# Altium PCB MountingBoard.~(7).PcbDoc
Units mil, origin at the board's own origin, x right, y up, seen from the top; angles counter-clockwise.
Board outline 3780 x 10000 mil, 4 copper layers (Top Layer, Internal Plane 1, Internal Plane 2, Bottom Layer); 27 components, 8 nets, 108 pads, 8 vias.
Unrouted connection lines stored in the file: 83.
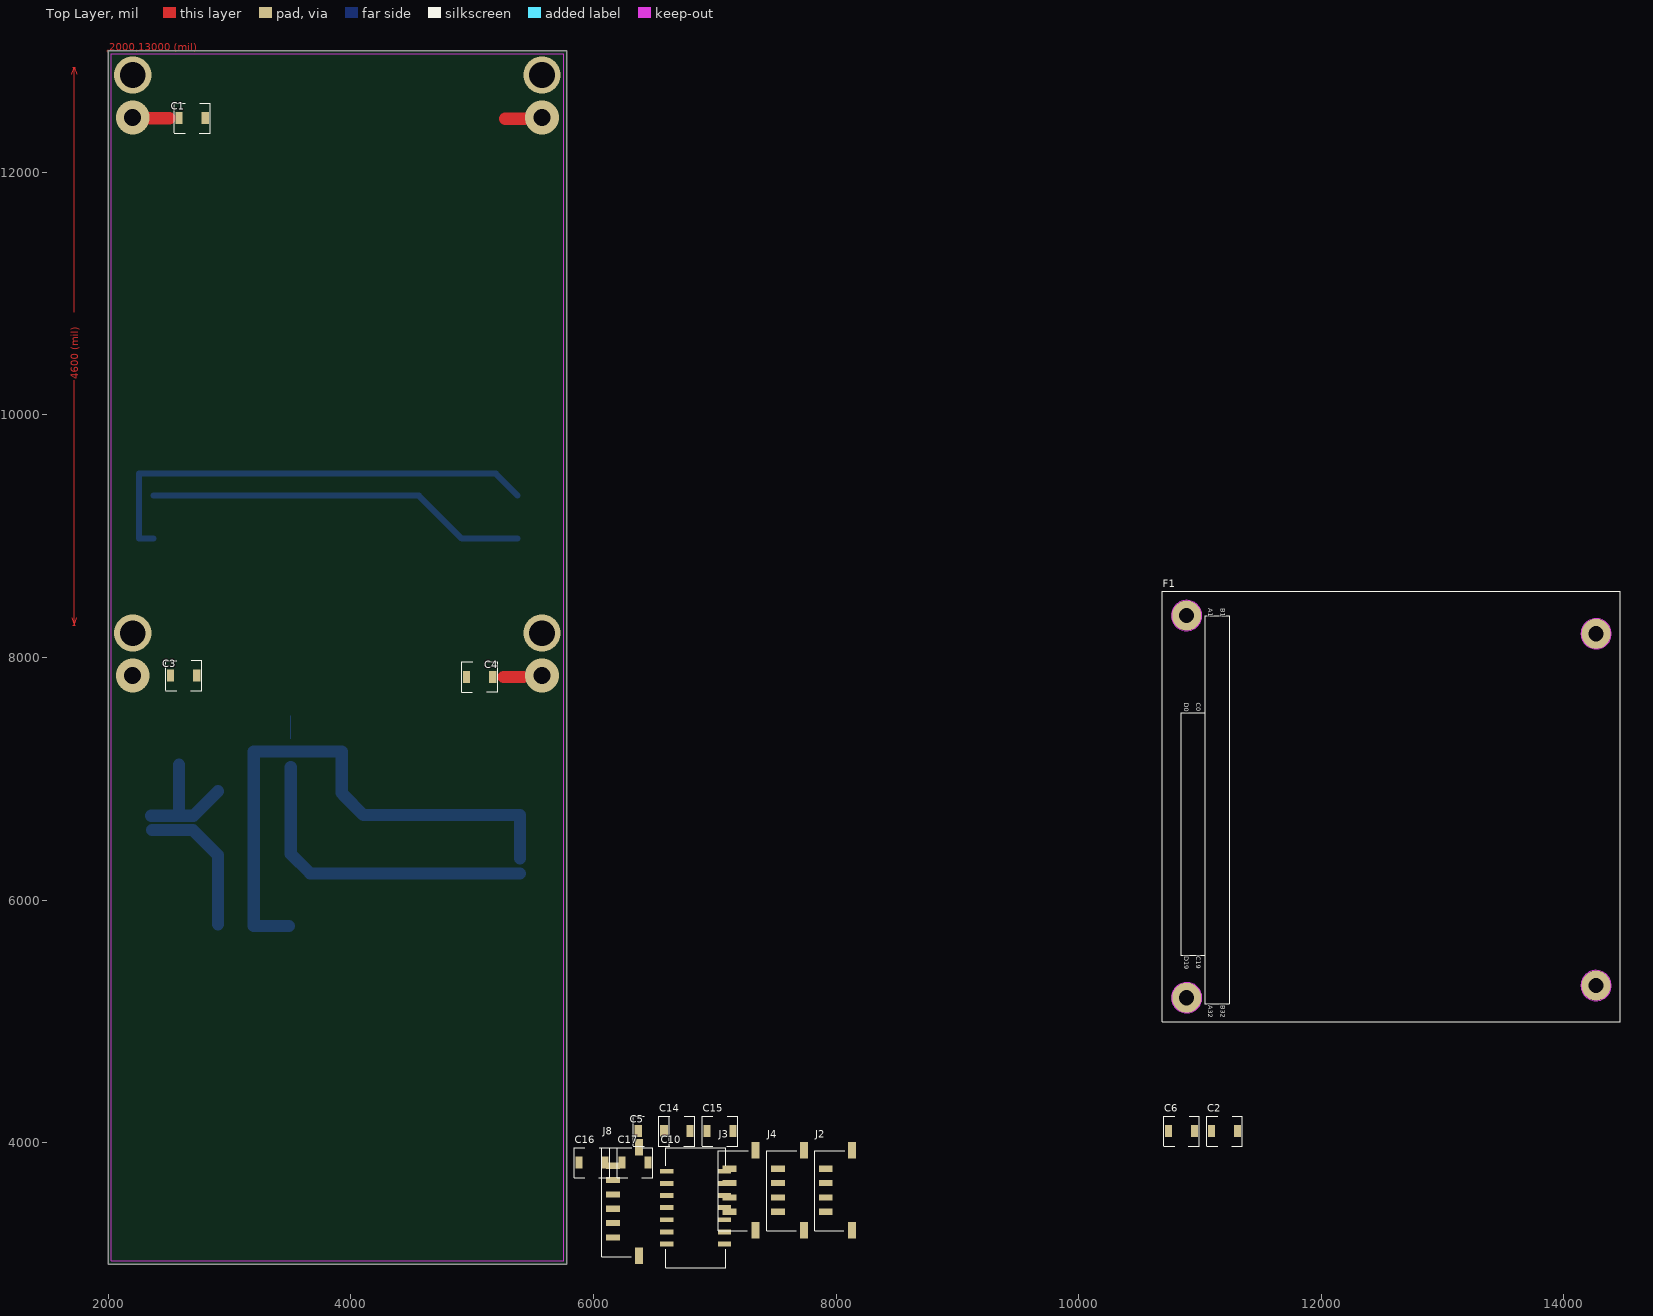
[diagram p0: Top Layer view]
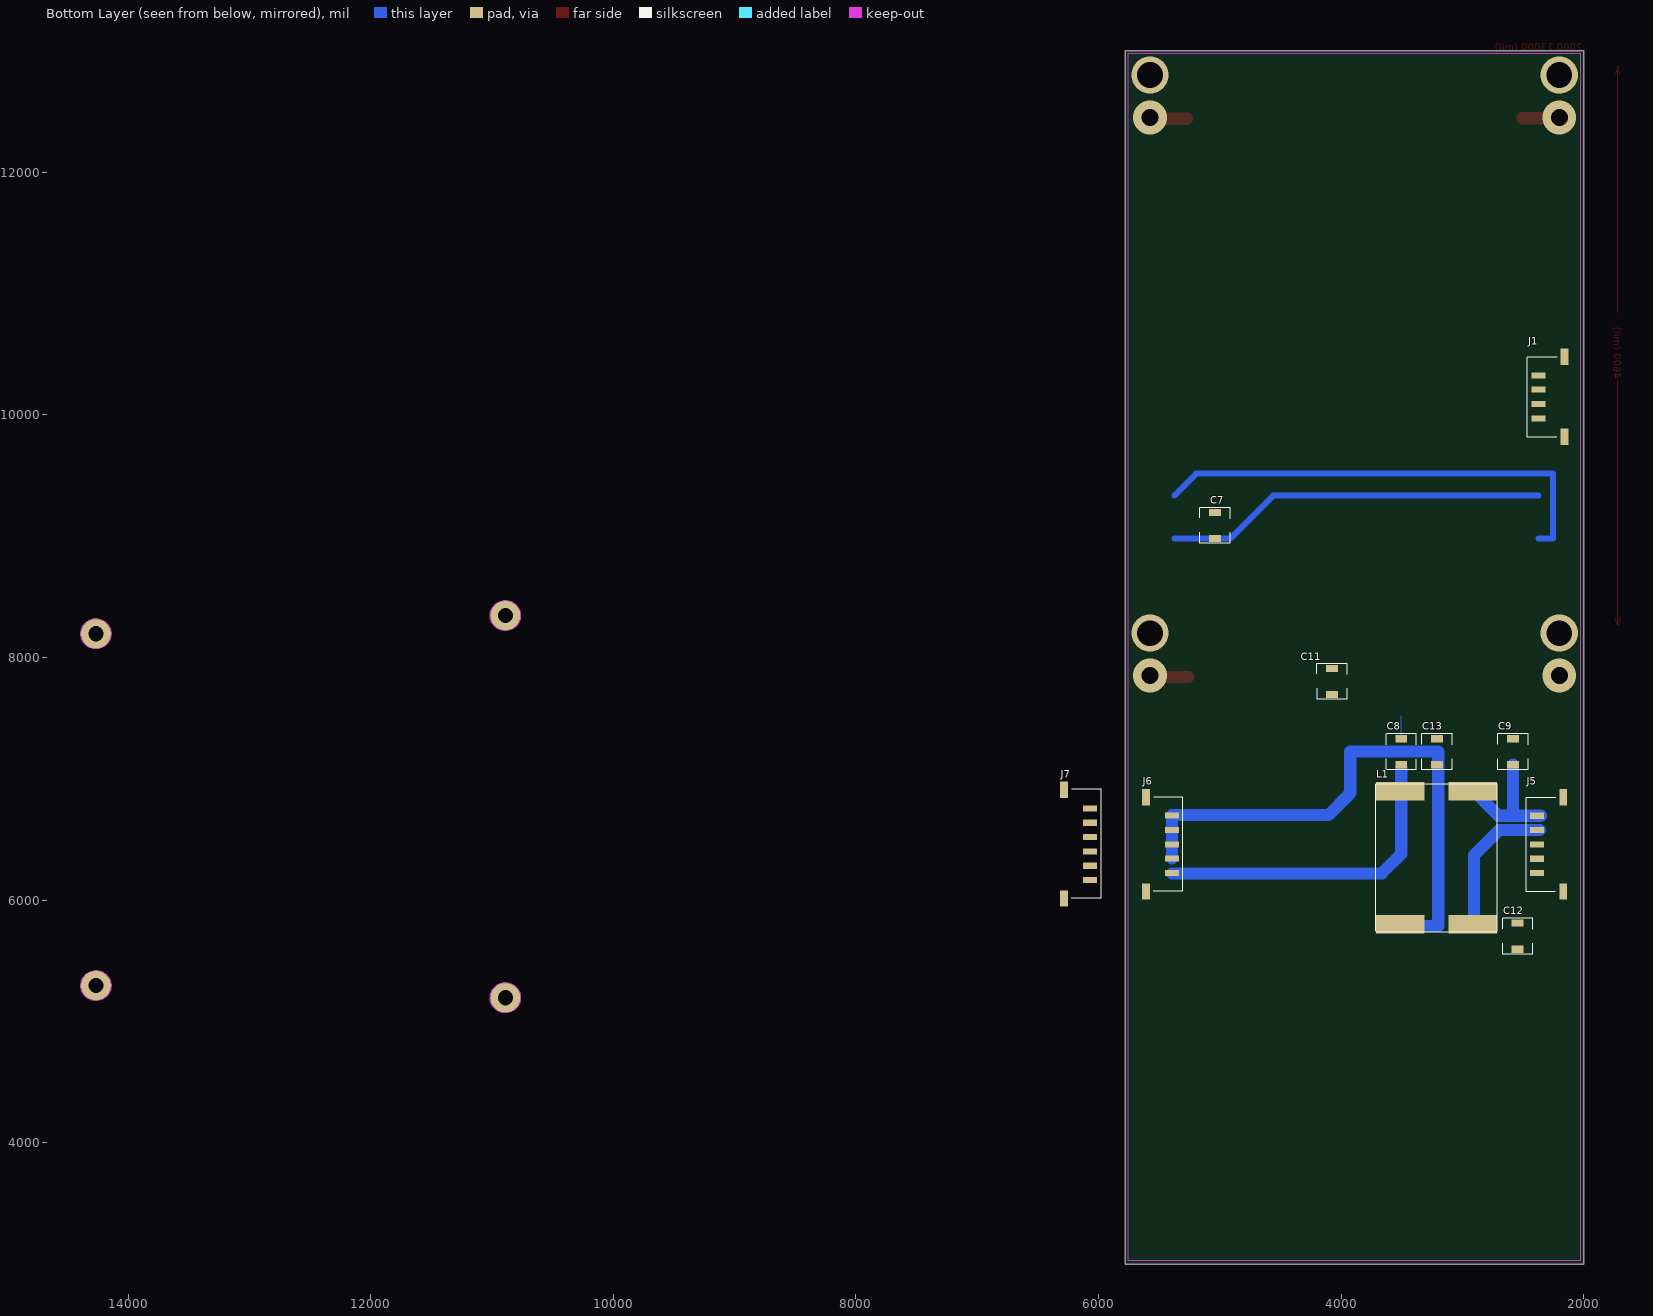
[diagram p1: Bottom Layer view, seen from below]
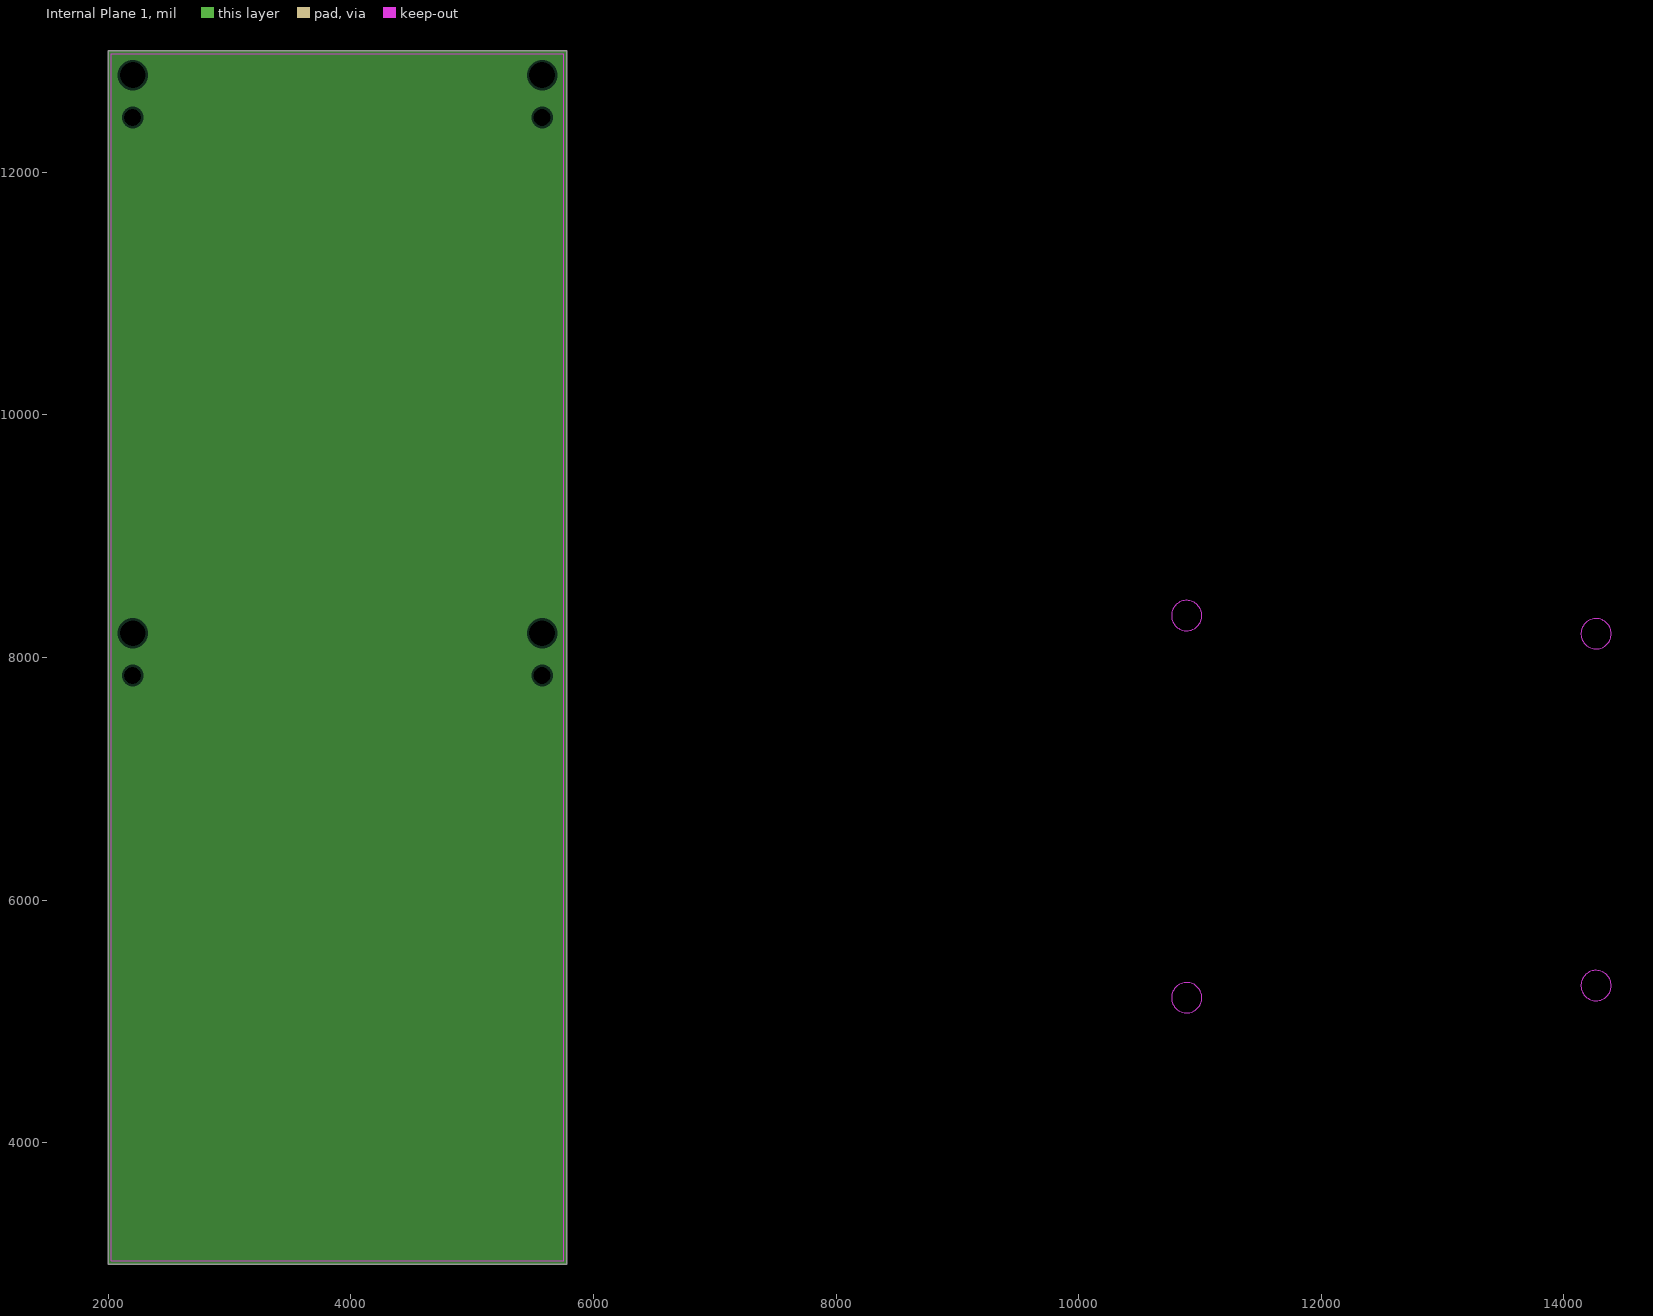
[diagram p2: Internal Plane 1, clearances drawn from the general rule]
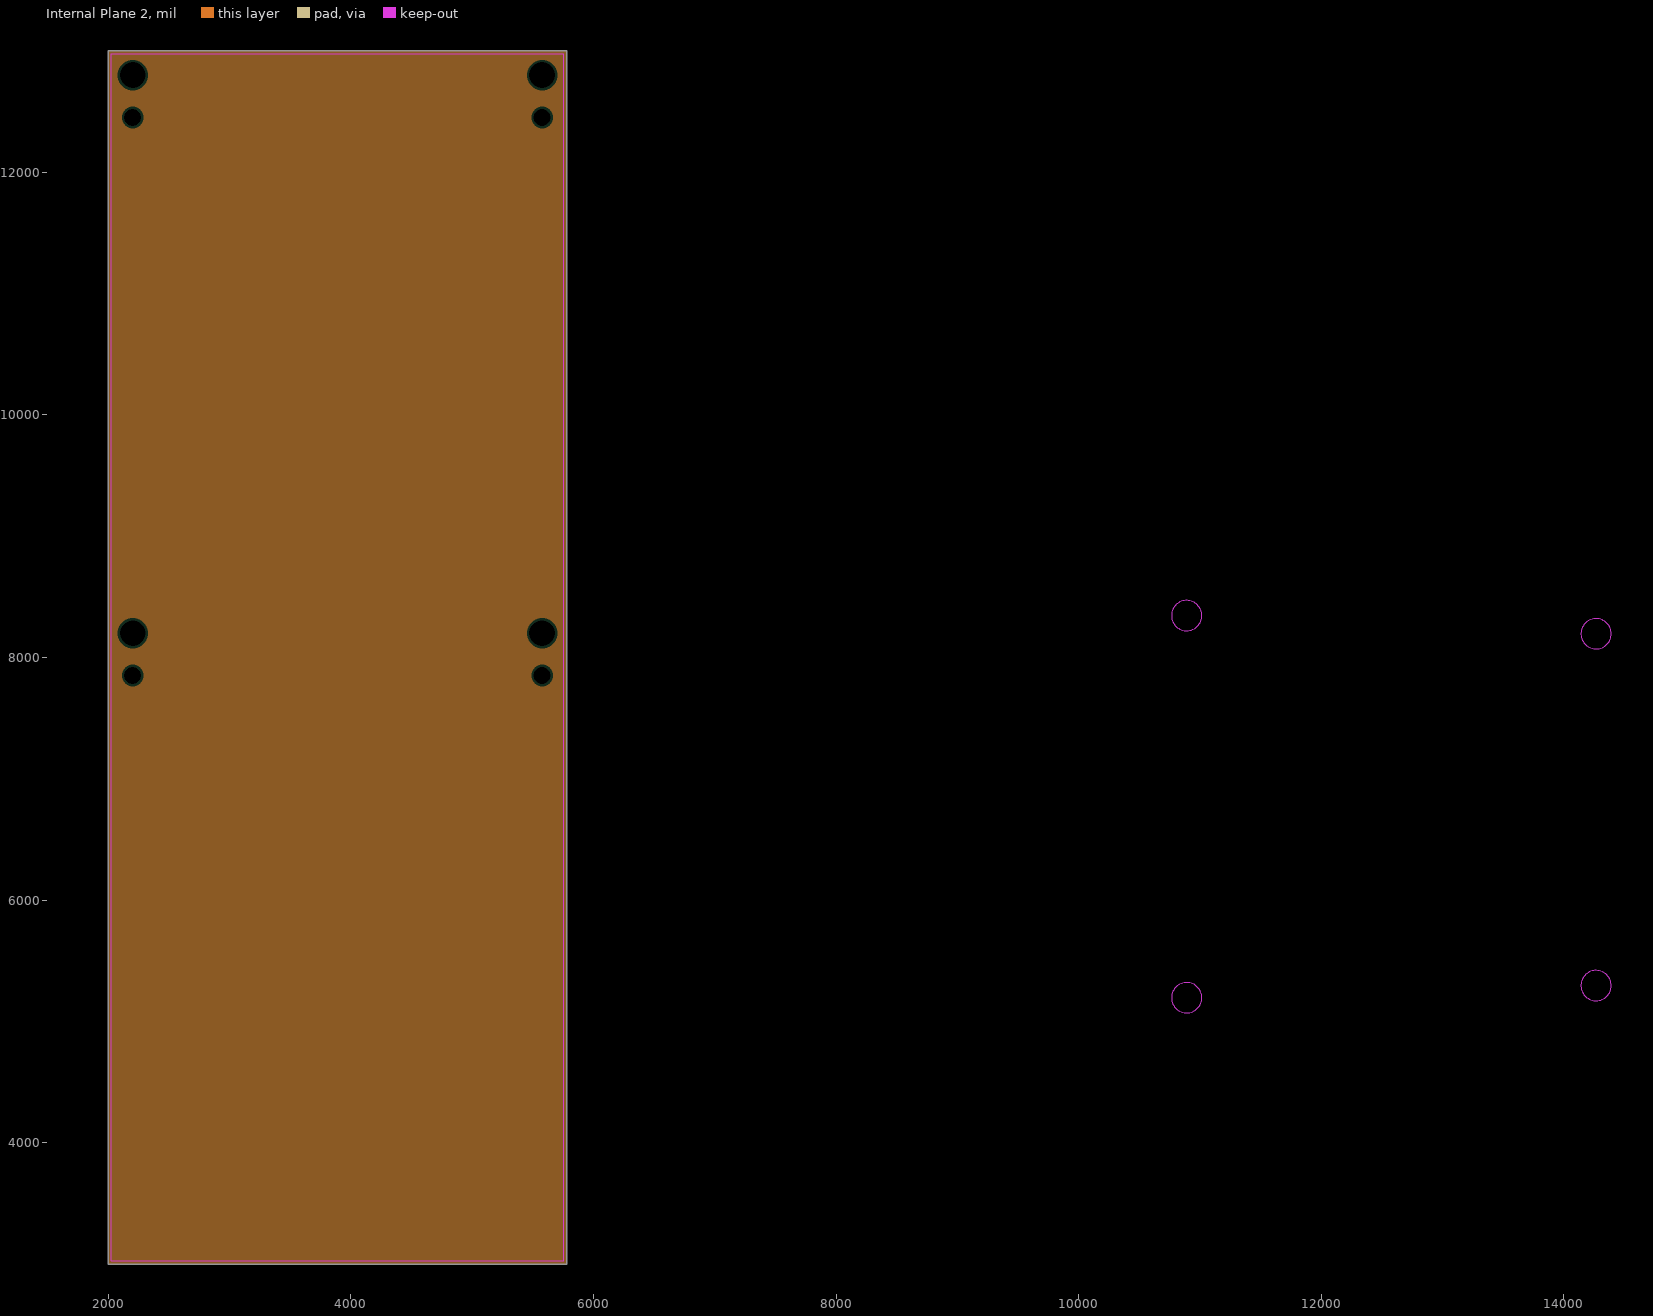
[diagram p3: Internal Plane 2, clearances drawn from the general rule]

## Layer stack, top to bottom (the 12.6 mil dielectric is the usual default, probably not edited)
Top Layer: signal copper 1.4
Dielectric: dielectric 12.6, FR-4, Dk 4.8
Internal Plane 1: plane copper 1.4
Dielectric: dielectric 12.6, FR-4, Dk 4.8
Internal Plane 2: plane copper 1.4
Dielectric: dielectric 12.6, FR-4, Dk 4.8
Bottom Layer: signal copper 1.4

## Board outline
2000,3000 5780,3000 5780,13000 2000,13000

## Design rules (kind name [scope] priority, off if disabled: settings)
Clearance [All] p1: gap=8
PlaneClearance [All] p1: clearance=20
PlaneConnect [All] p1: planeconnectstyle=Direct reliefexpansion=20 reliefentries=4 reliefconductorwidth=10 reliefairgap=10
PolygonConnect [All] p1: connectstyle=Direct reliefconductorwidth=10 reliefentries=4 polygonreliefangle="90 Angle"
RoomDefinition MountingBoard [InComponentClass('MountingBoard')] p1: confinementstyle=ConfineIn formatcopy=TRUE lockcomponents=FALSE outline 5825,2960 7145,2960 7145,4075 5825,4075
RoutingVias [All] p1: holewidth=28 width=50 viastyle="Through Hole" minholewidth=28 minwidth=50 maxholewidth=28 maxwidth=50
SilkscreenOverComponentPads [All] p1: minsilkscreentomaskgap=10
SolderMaskExpansion [All] p1: expansion=4
Width [All] p1: maxlimit=100 minlimit=10 preferedwidth=10 toplayer_maxwidth=10 minimp=50.000000 maximp=50.000000 favimp=50.000000
25 further rules are at their usual default settings.

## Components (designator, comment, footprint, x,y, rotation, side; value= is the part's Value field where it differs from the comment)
C1 "Cap Semi" 7163 2585,12445 r0 top
C2 "Cap Semi" 7163 11095,4095 r0 top
C3 "Cap Semi" 7163 2515,7850 r0 top
C4 "Cap Semi" 7163 5170,7840 r180 top
C5 "Cap Semi" 7163 6370,4095 r0 top
C6 "Cap Semi" 7163 10740,4095 r0 top
C7 "Cap Semi" 7163 5040,8980 r90 bottom
C8 "Cap Semi" 7163 3505,7330 r270 bottom
C9 "Cap Semi" 7163 2585,7115 r90 bottom
C10 "10uf" CAPSTICK-CS4-7-SMD 6605,3165 r90 top
C11 "Cap Semi" 7163 4075,7695 r90 bottom
C12 "Cap Semi" 7163 2545,5595 r90 bottom
C13 "Cap Semi" 7163 3210,7115 r90 bottom
C14 "Cap Semi" 7163 6580,4095 r0 top
C15 "Cap Semi" 7163 6935,4095 r0 top
C16 "Cap Semi" 7163 5880,3835 r0 top
C17 "Cap Semi" 7163 6235,3835 r0 top
F1 "PC104 Footprint" "PC104 Footprint" 10895,8345 r270 top
J1 "CON4_SMD" "Microfit3-1x4 SMT RA Nail" 2375,10325 r90 bottom
J2 "CON4_SMD" "Microfit3-1x4 SMT RA Nail" 7915,3785 r90 top
J3 "CON4_SMD" "Microfit3-1x4 SMT RA Nail" 7120,3785 r90 top
J4 "CON4_SMD" "Microfit3-1x4 SMT RA Nail" 7520,3785 r90 top
J5 "CON5_SMD" "Microfit3-1x5 SMT RA Nail" 2385,6695 r90 bottom locked
J6 "CON5_SMD" "Microfit3-1x5 SMT RA Nail" 5395,6223 r270 bottom locked
J7 "CON6_SMD" "Microfit3-1x6 SMT RA Nail" 6070,6165 r270 bottom
J8 "CON6_SMD" "Microfit3-1x6 SMT RA Nail" 6160,3810 r90 top
L1 "" Pulse_BigFoot 2715,6975 r270 bottom

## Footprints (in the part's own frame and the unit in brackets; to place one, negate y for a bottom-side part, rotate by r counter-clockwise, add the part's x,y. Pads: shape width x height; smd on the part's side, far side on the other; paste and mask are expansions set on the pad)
7163 [mm] "7.1 x 6.3 SMD"
  rect 1.5x2.5 smd: 1(0,0) 2(5.461,0)
  silkscreen extent -1.02,-3.17 6.48,3.17
CAPSTICK-CS4-7-SMD [mil] "Capstick CS4 case with 7 leads per side"
  rect 40x110 smd: 1(0,0) 1(100,0) 1(200,0) 1(300,0) 1(400,0) 1(500,0) 1(600,0) 2(0,-475) 2(100,-475) 2(200,-475) 2(300,-475) 2(400,-475) 2(500,-475) 2(600,-475)
  silkscreen extent -195,-485 795,10
"Microfit3-1x4 SMT RA Nail" [mil] "Microfit 3 Single Row 4 Position SMT Right Angle Nail"
  rect 50x115 smd: 1(0,0) 2(-118.11,0) 3(-236.22,0) 4(-354.33,0)
  rect 135x65 smd: nail(-506.5,-215.5) nail(152.5,-215.5)
  silkscreen extent -510,-155 150,90
"Microfit3-1x5 SMT RA Nail" [mil] "Microfit 3.0 Single Row SMT with Nails 5 Position"
  rect 50x115 smd: 1(0,0) 2(-118.11,0) 3(-236.22,0) 4(-354.33,0) 5(-472.44,0)
  rect 135x65 smd: nail(-624.5,-215.5) nail(152.5,-215.5)
  silkscreen extent -625,-155 150,90
"Microfit3-1x6 SMT RA Nail" [mil] "Microfit 3 Single Row 6 Position SMT Right Angle Nail"
  rect 50x115 smd: 1(0,0) 2(-118.11,0) 3(-236.22,0) 4(-354.33,0) 5(-472.44,0) 6(-590.55,0)
  rect 135x65 smd: nail(-743.5,-215.5) nail(152.5,-215.5)
  silkscreen extent -750,-155 150,90
"PC104 Footprint" [mil] "PC104 Footprint"
  round 250 hole 125: Mnt1(0,-5) Mnt2(3150,-5) Mnt3(3050,3370) Mnt4(150,3370)
  Keep-Out Layer circle w10: c0,-5 r125
  Keep-Out Layer circle w10: c150,3370 r125
  Keep-Out Layer circle w10: c3050,3370 r125
  Keep-Out Layer circle w10: c3150,-5 r125
  silkscreen extent -200,-205 3350,3570
Pulse_BigFoot [mil] "Pulse engineering big foot footprint"
  rect 155x400 smd: 1(77.5,-200) 2(77.5,-800) 3(1174.5,-200) 4(1174.5,-800)
  silkscreen extent 20,-1000 1240,0

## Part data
C1 C2 C3 C4 C5 C6 C7 C8 C9 C11 C12 C13 C14 C15 C16 C17: "Capacitor (Semiconductor SIM Model)"
C10: library part CAPACITOR, "Capacitor"
L1: library part "COMMON MODE CHOKE"

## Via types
v1: diameter 280, hole 140, Top Layer to Bottom Layer, 4 vias
v2: diameter 306, hole 213, Top Layer to Bottom Layer, 4 vias

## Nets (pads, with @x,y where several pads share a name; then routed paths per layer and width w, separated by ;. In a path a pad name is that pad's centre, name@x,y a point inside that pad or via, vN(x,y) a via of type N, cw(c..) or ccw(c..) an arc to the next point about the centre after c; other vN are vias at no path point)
48V+: C9.1 J5.1 L1.1 | length 1038.9
  Bottom Layer w100: J5.1@2355,6695 J5.1 2697.5,6695 ; 2585,6705 C9.1 ; 2702.5,6695 L1.1@2905,6897.5
48V-: C12.2 J5.2 L1.3 | length 1200.2
  Bottom Layer w100: J5.2@2360,6576.89 2698.11,6576.89 2905,6370 L1.3@2905,5800.5
+5V: C1.1 C7.1 C14.2 C15.2 J1.1 J2.1 J3.1 J4.1 J7.5 J7.6 J8.5 J8.6 | length 3146.6
  Bottom Layer w50: 2375,9334 4561,9334 4915,8980 5375,8980
+12V: C6.2 C11.2 C16.2 J1.4 J2.4 J3.4 J4.4 J7.4 J8.4
-12V: C17.2 J7.3 J8.3
CHASSIS: C1.2 C2.1 C3.1 C4.1 C5.1 C6.1 C7.2 C8.1 C9.2 C11.1 C12.1 C13.2 C14.1 C15.1 C16.1 C17.1 J1.nail J2.nail J3.nail J4.nail J7.nail J8.nail | length 351.9
  Top Layer w100: 5260,7840 5421.85,7840
  Bottom Layer w10: C8.1 3505,7520
  other v1: 2202.5,7850 5577.5,7850
"EDGETECH GROUND": C2.2 C3.2 C4.2 C5.2 C10.2 C13.1 J1.2 J1.3 J2.2 J2.3 J3.2 J3.3 J4.2 J4.3 J6.2 J6.3 J6.4 J6.5 J7.1 J7.2 J8.1 J8.2 L1.4 | length 4683.8
  Bottom Layer w100: L1.4@3489.5,5785 3200,5785 3200,7225 3925,7225 3925,6885 ; 3935,6870 4105,6700 5395,6700 J6.2
  other v2: 2202.5,8200 5577.5,8200 2202.5,12800 5577.5,12800
"FILTER 48V+": C8.2 C10.1 J6.1 L1.2 | length 2671.3
  Bottom Layer w100: C8.2@3505,7095 3505,6380 3665,6220 J6.1@5395,6220
pads on no net: F1.Mnt1 F1.Mnt2 F1.Mnt3 F1.Mnt4 J5.3 J5.4 J5.5 J5.nail J6.nail
copper on no net: | length 8544.4
  Top Layer w10: 1699.01,8325.91 1719.01,8265.91 ; 1699.01,12805.91 1719.01,12865.91 ; 1709.01,8265.91 1729.01,8265.91 ; 1709.01,12865.91 1729.01,12865.91 ; 1719.01,10285 1719.01,8265.91 ; 1719.01,10846.83 1719.01,12865.91 ; 1739.01,8325.91 1719.01,8265.91 ; 1739.01,12805.91 1719.01,12865.91 ; 1990,13000 2010,13000 ; 2000,12990 2000,13010
  Top Layer w100: 2345,12445 2506.85,12445 ; 5273.15,12440 5435,12440
  Bottom Layer w50: 2375,8979.67 2255.33,8979.67 2255,8980 2255,9514.67 5194.66,9514.67 5375,9334.33
  other v1: 2202.5,12450 5577.5,12450

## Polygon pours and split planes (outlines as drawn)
no net on Internal Plane 1 (split plane): 5780,3000 2000,3000 2000,13000 5780,13000
no net on Internal Plane 2 (split plane): 5780,3000 2000,3000 2000,13000 5780,13000

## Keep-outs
Keep-Out Layer:
  lines w10: 2025,3025 2025,12975 5755,12975 5755,3025 2025,3025

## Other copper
Top Layer:
  text "2000,13000 (mil)" at 2010,13000 h60
  text "4600 (mil)" at 1755,10295 h60 r90

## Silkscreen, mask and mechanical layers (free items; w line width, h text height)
Drill Drawing:
  text ".LEGEND" at 5980,3200 h60
  text "Drill Drawing." at 5980,3100 h60

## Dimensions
2202.5,12800 to 5577.5,12800 on Top Layer
2025,3025 to 2025,12975 on Mechanical 1
2025,3025 to 5755,3025 on Mechanical 1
